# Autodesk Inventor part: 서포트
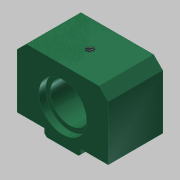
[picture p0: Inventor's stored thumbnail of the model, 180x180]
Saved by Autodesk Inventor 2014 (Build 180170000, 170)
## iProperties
Created: 2019-04
Part Number: 서포트
Material: 알루미늄 6061
Document SubType Name: Modeling
Designer: mduedu
Density: 1 g/cm^3
Appearance: Smooth - Dark Sea Green
Author: mduedu
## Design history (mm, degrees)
sketch "스케치1"
  geometry: L1 (3, 20)-(31, 20); L2 (31, 20)-(31, -20); L3 (31, -20)-(3, -20); L4 (0, -8)-(0, 8); L5 (0, 8)-(3, 8); L6 (3, 8)-(3, 20); L7 (0, 0)-(31, 0); L8 (0, -8)-(3, -8); L9 (3, -8)-(3, -20); 1 further point
  constraints: 18 end point, 3 symmetric about line, 2 horizontal, 2 midpoint, 2 parallel, 2 perpendicular, 1 coincident
  dimensions: "d3" = 31 distance between parallel lines of L4 L2; "d5" = 16 distance of L4.start L4.end; "d6" = 40 distance between parallel lines of L3 L1; "d7" = 3 distance between parallel lines of L4 L9
extrude "돌출1" new body sketch "스케치1" distance "d8" = 24; taper "d9" = 0 deg
chamfer "모따기1" distance "d10" = 4; stored, may be unused: second distance "d11" = 2, angle "d12" = 45 deg
chamfer "모따기2" distance "d13" = 1; stored, may be unused: second distance "d14" = 2, angle "d15" = 45 deg
sketch "스케치2"
  geometry: L1 (7, 0)-(-7, 0) reference; L2 (20, 3)-(8, 3) reference; 3 further points
  constraints: 1 midpoint, 1 vertical alignment
  dimensions: "d24" = 12 distance from line of point (0, 15) L2
hole "구멍1" sketch "스케치2" at (0, 15) diameter "d17" = 17; stored, may be unused: countersink angle "d21" = 90 deg, drill point angle "d23" = 118 deg; dims "d18" = 6, "d19" = 21, "d20" = 3, "d22" = 8
sketch "스케치3"
  geometry: L1 (0, 32)-(0, 0) reference; 3 further points
  constraints: 1 horizontal alignment, 1 midpoint
  dimensions: "d25" = 12 distance from line of point (12, 16) L1
hole "구멍2" sketch "스케치3" at (12, 16) diameter "d26" = 3.242; stored, may be unused: countersink angle "d30" = 90 deg, drill point angle "d32" = 118 deg; dims "d27" = 6, "d28" = 21, "d29" = 3, "d31" = 8
sketch "스케치4"
  geometry: L1 (0, -8)-(24, -8); L2 (24, 0.5)-(24, -16.5) reference; L3 (0, -28)-(0, -24) reference; 4 further points
  constraints: 2 end point, 2 symmetric about line, 1 horizontal, 1 horizontal alignment, 1 midpoint
  dimensions: "d33" = 6 distance from line of point (6, -22) L3; "d34" = 12 distance of point (18, -22) point (6, -22); "d35" = 28 distance of point (6, 6) point (6, -22); "d36" = 14 distance from line of point (6, -22) L1 (derived)
hole "구멍3" sketch "스케치4" at (6, -22), (18, -22), (18, 6), (6, 6) diameter "d37" = 3.242; stored, may be unused: countersink angle "d41" = 90 deg, drill point angle "d43" = 118 deg; dims "d38" = 9, "d39" = 21, "d40" = 3, "d42" = 11
node "솔리드1"
